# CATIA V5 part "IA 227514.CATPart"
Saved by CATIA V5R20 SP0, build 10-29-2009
Part number: IA 227514
Revision: ANY
Definition: UNKNOWN
Nomenclature: IA 227514
Source: Unknown
Bounding box of the stored display mesh (mm): x -1.102 to 1.102, y -0.001 to 7.75, z -1.102 to 1.102
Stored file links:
  C:\Users\Utente\Desktop\IO LAVORO\3D X SITO CF\CUMSA\3D files FA\FA 042212-21\IA 227514.CATPart

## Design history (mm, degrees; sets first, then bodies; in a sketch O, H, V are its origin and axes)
Body1 "Cortar-Extruir3" (main body)
  Solid1: solid without history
